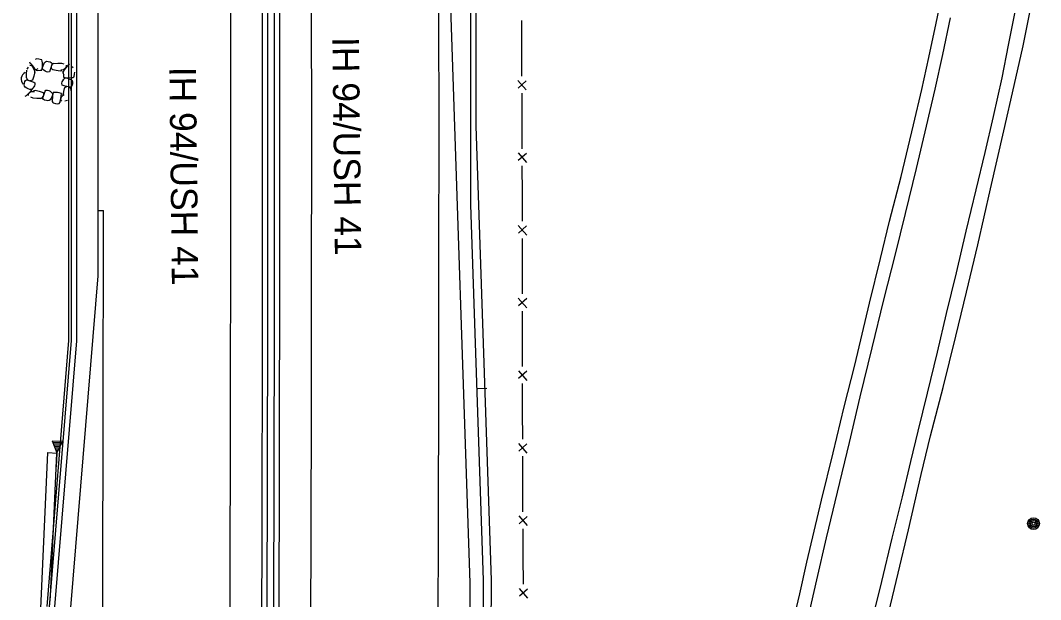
# Model space of a CAD drawing. Extents: x 588843 to 2552415, y 180129 to 269402.
# Drawn here: x 593926.7 to 594311.3, y 187872.4 to 188090.9 of the extents above; entities that cross this region are included whole.
import ezdxf

# ---------------------------------------------------------------- set-up
doc = ezdxf.new("R2010")
doc.units = 0
for name, color, linetype in [('Default', 7, 'Continuous'), ('E_DRN', 7, 'Continuous'), ('E_DRN_RipRap', 7, 'Continuous'), ('E_FEN_P', 7, 'Continuous'), ('E_MISCPROP', 7, 'Continuous'), ('E_RDWY', 7, 'Continuous'), ('E_RDWY_Gravel', 7, 'Continuous'), ('E_RDWY_Text', 7, 'Continuous'), ('P_BMGRD', 7, 'Continuous'), ('P_RDWY_BarrierConc', 7, 'Continuous'), ('P_RDWY_C_and_G', 7, 'Continuous'), ('P_RDWY_C_and_GBack', 7, 'Continuous'), ('P_RDWY_C_and_GFace', 7, 'Continuous'), ('P_RDWY_PavtEdge', 7, 'Continuous'), ('P_RDWY_ShldAgg', 7, 'Continuous'), ('P_RDWY_ShldPaved', 7, 'Continuous')]:
    doc.layers.add(name, color=color, linetype=linetype)

# ---------------------------------------------------------------- blocks, each defined once
blk = doc.blocks.new('POLE')
at = {"layer": 'Default'}
for radius in [4.46, 3.35, 2.23, 1.12]:
    blk.add_circle((0, 0), radius, dxfattribs=at)
blk = doc.blocks.new('CULV2')
at = {"layer": 'E_DRN'}
blk.add_arc((19.7, 14.8), 24.6, 216.8699, 323.1301, dxfattribs=at)

msp = doc.modelspace()

# ---------------------------------------------------------------- linework, layer by layer
at = {"layer": 'E_DRN_RipRap'}
for p, q in [((593932.94, 188076.36), (593932.27, 188076.17)), ((593933.7, 188076.29), (593932.94, 188076.36)), ((593934.63, 188076.07), (593933.7, 188076.29)), ((593934.75, 188075.98), (593934.63, 188076.07)), ((593934.96, 188075.55), (593934.75, 188075.98)), ((593928.97, 188070.74), (593929.1, 188072.07)), ((593929.22, 188072.49), (593929.75, 188073.3)), ((593930.19, 188075.3), (593930.34, 188074.69)), ((593930.28, 188073.98), (593930.89, 188073.91)), ((593930.34, 188074.69), (593930.61, 188074.44)), ((593930.61, 188074.44), (593931.27, 188073.7)), ((593930.89, 188073.91), (593931.45, 188073.25)), ((593931.27, 188073.7), (593931.86, 188072.92)), ((593931.45, 188073.25), (593931.69, 188072.61)), ((593931.63, 188072.74), (593932.02, 188071.85)), ((593931.86, 188072.92), (593932.57, 188072.29)), ((593932.57, 188072.29), (593933.38, 188072.77)), ((593932.59, 188072.1), (593933.13, 188071.99)), ((593933.13, 188071.99), (593934.11, 188072.09)), ((593934.11, 188072.09), (593934.77, 188072.12)), ((593934.77, 188072.12), (593935.03, 188073.37)), ((593934.97, 188074.92), (593934.96, 188075.55)), ((593935, 188074.05), (593934.97, 188074.92)), ((593935.03, 188073.37), (593935, 188074.05)), ((593935.02, 188073.16), (593935.22, 188073.8)), ((593935.09, 188072.6), (593935.02, 188073.16)), ((593935.21, 188072.46), (593935.09, 188072.6)), ((593935.53, 188072.13), (593935.21, 188072.46)), ((593935.22, 188073.8), (593935.49, 188074.39)), ((593935.49, 188074.39), (593935.79, 188075.02)), ((593936.03, 188071.76), (593935.53, 188072.13)), ((593935.79, 188075.02), (593936.1, 188075.27)), ((593936.1, 188075.27), (593936.6, 188075.45)), ((593936.6, 188075.45), (593937.15, 188075.38)), ((593937.15, 188075.38), (593937.88, 188075.23)), ((593938.11, 188072.65), (593937.82, 188071.85)), ((593937.88, 188075.23), (593938.33, 188074.97)), ((593938.52, 188074.2), (593938.11, 188072.65)), ((593938.46, 188073.96), (593938.25, 188073.21)), ((593938.59, 188072.43), (593938.25, 188073.21)), ((593938.33, 188074.97), (593938.53, 188074.7)), ((593938.85, 188074.44), (593938.46, 188073.96)), ((593938.53, 188074.7), (593938.52, 188074.2)), ((593938.97, 188072.28), (593938.59, 188072.43)), ((593939.36, 188074.69), (593938.85, 188074.44)), ((593940.13, 188071.99), (593938.97, 188072.28)), ((593939.36, 188074.69), (593940.84, 188074.81)), ((593941.69, 188071.74), (593940.13, 188071.99)), ((593940.84, 188074.81), (593942.17, 188074.75)), ((593942.9, 188072.3), (593941.94, 188072.17)), ((593942.17, 188074.75), (593943.1, 188074.46)), ((593943.24, 188072.2), (593942.77, 188071.38)), ((593943.47, 188072.67), (593942.9, 188072.3)), ((593943.87, 188072.94), (593943.24, 188072.2)), ((593944, 188073.35), (593943.47, 188072.67)), ((593944.46, 188073.74), (593943.87, 188072.94)), ((593943.95, 188073.96), (593944, 188073.35)), ((593944.65, 188074.06), (593944.46, 188073.74)), ((593945.22, 188074.33), (593944.65, 188074.06)), ((593946.55, 188073), (593946.01, 188073.44)), ((593928.38, 188067.8), (593928.67, 188068.24)), ((593928.67, 188068.24), (593928.95, 188068.42)), ((593928.95, 188068.42), (593929.45, 188068.39)), ((593929, 188069.26), (593928.97, 188070.74)), ((593929, 188069.26), (593929.23, 188068.73)), ((593929.23, 188068.73), (593929.68, 188068.31)), ((593929.45, 188068.39), (593930.98, 188067.89)), ((593929.68, 188068.31), (593930.42, 188068.07)), ((593931.22, 188068.37), (593930.42, 188068.07)), ((593931.39, 188068.74), (593931.22, 188068.37)), ((593931.74, 188069.88), (593931.39, 188068.74)), ((593932.08, 188071.43), (593931.74, 188069.88)), ((593932.02, 188071.85), (593932, 188071.23)), ((593936.51, 188071.52), (593936.03, 188071.76)), ((593936.98, 188071.38), (593936.51, 188071.52)), ((593937.66, 188071.49), (593936.98, 188071.38)), ((593937.82, 188071.85), (593937.66, 188071.49)), ((593942.3, 188071.88), (593941.69, 188071.74)), ((593942.45, 188067.66), (593942.67, 188068.15)), ((593942.56, 188071.76), (593942.85, 188070.87)), ((593942.67, 188068.15), (593943.03, 188068.66)), ((593942.82, 188071.05), (593942.95, 188070.07)), ((593942.85, 188070.87), (593943.07, 188070.36)), ((593942.95, 188070.07), (593943, 188069.42)), ((593943, 188069.42), (593944.25, 188069.19)), ((593943.03, 188068.66), (593943.36, 188068.99)), ((593943.36, 188068.99), (593943.49, 188069.11)), ((593943.49, 188069.11), (593944.05, 188069.2)), ((593944.05, 188069.2), (593944.69, 188069.02)), ((593944.25, 188069.19), (593944.94, 188069.25)), ((593944.69, 188069.02), (593945.29, 188068.76)), ((593944.94, 188069.25), (593945.8, 188069.3)), ((593945.29, 188068.76), (593945.93, 188068.48)), ((593945.8, 188069.3), (593946.43, 188069.33)), ((593945.93, 188068.48), (593946.18, 188068.18)), ((593946.18, 188068.18), (593946.38, 188067.68)), ((593946.43, 188069.33), (593946.86, 188069.55)), ((593946.86, 188069.55), (593946.94, 188069.68)), ((593946.94, 188069.68), (593947.13, 188070.61)), ((593947.13, 188070.61), (593947.18, 188071.37)), ((593928.1, 188066.54), (593928.19, 188067.09)), ((593928.25, 188066.03), (593928.1, 188066.54)), ((593928.19, 188067.09), (593928.38, 188067.8)), ((593928.48, 188065.71), (593928.25, 188066.03)), ((593929.1, 188065.37), (593928.48, 188065.71)), ((593929.67, 188065.07), (593929.1, 188065.37)), ((593930.3, 188064.84), (593929.67, 188065.07)), ((593930.86, 188064.88), (593930.3, 188064.84)), ((593930.67, 188064.2), (593931.24, 188064.95)), ((593931, 188064.99), (593930.86, 188064.88)), ((593930.98, 188067.89), (593931.76, 188067.56)), ((593931.36, 188065.29), (593931, 188064.99)), ((593931.76, 188065.77), (593931.36, 188065.29)), ((593931.6, 188064.44), (593932.22, 188064.54)), ((593931.76, 188067.56), (593932.11, 188067.39)), ((593932.02, 188066.24), (593931.76, 188065.77)), ((593932.18, 188066.7), (593932.02, 188066.24)), ((593932.11, 188067.39), (593932.18, 188066.7)), ((593932.22, 188064.54), (593933.76, 188064.19)), ((593936.08, 188064.18), (593936.25, 188064.53)), ((593936.25, 188064.53), (593936.95, 188064.6)), ((593936.95, 188064.6), (593937.4, 188064.43)), ((593937.4, 188064.43), (593937.87, 188064.17)), ((593942.33, 188067.19), (593942.45, 188067.66)), ((593942.46, 188066.5), (593942.33, 188067.19)), ((593942.82, 188066.36), (593942.46, 188066.5)), ((593943.63, 188066.1), (593942.82, 188066.36)), ((593943.03, 188064.05), (593943.28, 188065.22)), ((593943.28, 188065.22), (593943.43, 188065.6)), ((593943.43, 188065.6), (593944.2, 188065.97)), ((593945.19, 188065.73), (593943.63, 188066.1)), ((593944.95, 188065.79), (593944.2, 188065.97)), ((593945.43, 188065.41), (593944.95, 188065.79)), ((593945.68, 188065.74), (593945.19, 188065.73)), ((593945.71, 188064.9), (593945.43, 188065.41)), ((593945.95, 188065.94), (593945.68, 188065.74)), ((593945.71, 188064.9), (593945.87, 188063.43)), ((593946.2, 188066.4), (593945.95, 188065.94)), ((593946.33, 188067.13), (593946.2, 188066.4)), ((593946.38, 188067.68), (593946.33, 188067.13)), ((593928.44, 188062.33), (593929.04, 188062.53)), ((593929.04, 188062.53), (593929.27, 188062.83)), ((593929.27, 188062.83), (593929.95, 188063.55)), ((593929.74, 188062.54), (593929.76, 188063.15)), ((593929.76, 188063.15), (593930.38, 188063.76)), ((593929.95, 188063.55), (593930.67, 188064.2)), ((593930.38, 188063.76), (593931, 188064.05)), ((593931.55, 188061.57), (593930.64, 188061.92)), ((593931, 188064.05), (593931.96, 188064.06)), ((593932.87, 188061.42), (593931.55, 188061.57)), ((593934.35, 188061.45), (593932.87, 188061.42)), ((593933.76, 188064.19), (593934.9, 188063.83)), ((593934.35, 188061.45), (593934.88, 188061.67)), ((593934.88, 188061.67), (593935.31, 188062.12)), ((593934.9, 188063.83), (593935.27, 188063.65)), ((593935.19, 188061.39), (593935.23, 188061.89)), ((593935.37, 188061.11), (593935.19, 188061.39)), ((593935.23, 188061.89), (593935.74, 188063.41)), ((593935.27, 188063.65), (593935.56, 188062.85)), ((593935.31, 188062.12), (593935.56, 188062.85)), ((593935.8, 188060.81), (593935.37, 188061.11)), ((593935.74, 188063.41), (593936.08, 188064.18)), ((593936.52, 188060.62), (593935.8, 188060.81)), ((593937.06, 188060.52), (593936.52, 188060.62)), ((593937.58, 188060.67), (593937.06, 188060.52)), ((593937.9, 188060.89), (593937.58, 188060.67)), ((593937.87, 188064.17), (593938.34, 188063.76)), ((593938.24, 188061.5), (593937.9, 188060.89)), ((593938.55, 188062.07), (593938.24, 188061.5)), ((593938.34, 188063.76), (593938.64, 188063.41)), ((593938.79, 188062.7), (593938.55, 188062.07)), ((593938.64, 188063.41), (593938.75, 188063.26)), ((593938.72, 188060.94), (593938.69, 188060.31)), ((593938.75, 188061.81), (593938.72, 188060.94)), ((593938.75, 188063.26), (593938.79, 188062.7)), ((593938.76, 188062.5), (593938.75, 188061.81)), ((593939.1, 188063.72), (593938.76, 188062.5)), ((593939.76, 188063.71), (593939.1, 188063.72)), ((593940.74, 188063.75), (593939.76, 188063.71)), ((593941.27, 188063.6), (593940.74, 188063.75)), ((593942.16, 188063.28), (593941.27, 188063.6)), ((593941.72, 188060.03), (593941.74, 188060.4)), ((593941.74, 188060.4), (593941.89, 188061.38)), ((593941.89, 188061.38), (593942.11, 188062.33)), ((593941.96, 188060.95), (593942.13, 188061.8)), ((593942.3, 188060.43), (593941.96, 188060.95)), ((593942.11, 188062.33), (593942.16, 188063.28)), ((593942.13, 188061.8), (593942.47, 188062.39)), ((593942.47, 188062.39), (593943.25, 188062.95)), ((593942.71, 188062.95), (593943.13, 188063.41)), ((593942.82, 188062.48), (593943.03, 188064.05)), ((593944.44, 188060.65), (593943.51, 188060.38)), ((593945.87, 188063.43), (593945.85, 188062.09)), ((593938.69, 188060.31), (593938.87, 188059.87)), ((593938.87, 188059.87), (593938.99, 188059.77)), ((593938.99, 188059.77), (593939.91, 188059.5)), ((593939.91, 188059.5), (593940.66, 188059.37)), ((593940.66, 188059.37), (593941.34, 188059.52)), ((593941.34, 188059.52), (593941.72, 188060.03))]:
    msp.add_line(p, q, dxfattribs=at)
at = {"layer": 'E_FEN_P'}
for p, q in [((594114.21, 188068.27), (594117.39, 188064.64)), ((594117.38, 188068.11), (594114.29, 188065.37)), ((594114.29, 188040.89), (594117.47, 188037.25)), ((594117.46, 188040.73), (594114.37, 188037.98)), ((594114.37, 188013.5), (594117.56, 188009.87)), ((594117.55, 188013.34), (594114.45, 188010.59)), ((594114.41, 187986.12), (594117.59, 187982.48)), ((594117.58, 187985.96), (594114.48, 187983.21)), ((594114.44, 187958.73), (594117.61, 187955.09)), ((594117.61, 187958.57), (594114.51, 187955.83)), ((594114.47, 187931.35), (594117.64, 187927.71)), ((594117.64, 187931.18), (594114.54, 187928.44)), ((594114.59, 187903.96), (594117.78, 187900.33)), ((594117.76, 187903.81), (594114.67, 187901.05)), ((594114.72, 187876.57), (594117.92, 187872.95)), ((594117.9, 187876.42), (594114.81, 187873.67))]:
    msp.add_line(p, q, dxfattribs=at)
for points in [[(594115.61, 188090.8), (594115.64, 188080.34)], [(594115.64, 188080.34), (594115.67, 188069.89)], [(594115.69, 188063.41), (594115.72, 188053.7), (594115.72, 188052.96)], [(594115.72, 188052.96), (594115.75, 188042.5)], [(594115.77, 188036.03), (594115.8, 188025.57)], [(594115.8, 188025.57), (594115.83, 188015.11)], [(594115.85, 188008.64), (594115.85, 188008.61), (594115.86, 187998.19)], [(594115.86, 187998.19), (594115.87, 187987.73)], [(594115.88, 187981.26), (594115.89, 187970.8)], [(594115.89, 187970.8), (594115.9, 187960.34)], [(594115.91, 187953.87), (594115.92, 187943.41)], [(594115.92, 187943.41), (594115.93, 187932.96)], [(594115.94, 187926.49), (594115.99, 187916.03)], [(594115.99, 187916.03), (594116.04, 187905.57)], [(594116.08, 187899.1), (594116.13, 187888.64)], [(594116.13, 187888.64), (594116.18, 187878.19)]]:
    msp.add_lwpolyline(points, dxfattribs=at)
at = {"layer": 'E_RDWY'}
for points in [[(594228.57, 187780.63), (594232.33, 187798.24), (594235.82, 187813.68), (594239.52, 187829.79), (594243.61, 187847.13), (594247.57, 187863.55), (594251.39, 187879.2), (594255.33, 187895.54), (594259.23, 187911.13), (594262.33, 187924.57), (594265.09, 187935.9), (594268.62, 187950.26), (594272.41, 187965.71), (594275.87, 187980.35), (594279.56, 187995.66), (594283.28, 188011.39), (594287.05, 188026.98), (594290.42, 188041.06), (594293.56, 188054.66), (594296.78, 188069.2), (594299.2, 188081.49), (594302.12, 188095.96)], [(594204.12, 187779.52), (594208.85, 187801.44), (594212.44, 187817.45), (594216.12, 187833.75), (594219.89, 187849.7), (594223.26, 187863.88), (594226.91, 187879.94), (594230.58, 187895.72), (594234.73, 187912.94), (594239.27, 187931.72), (594243.32, 187948.86), (594247.83, 187967.41), (594252.22, 187985.44), (594256.55, 188002.76), (594260.32, 188018.1), (594264.49, 188035.08), (594268.29, 188050.96), (594271.53, 188064.91), (594274.5, 188078.06), (594277.28, 188091.89)]]:
    msp.add_lwpolyline(points, dxfattribs=at)
at = {"layer": 'E_RDWY_Gravel'}
for points in [[(594198.98, 187780.6), (594201.99, 187794.32), (594206.34, 187814.37), (594209.66, 187828.73), (594213.65, 187845.12), (594217.26, 187860.85), (594220.48, 187874.65), (594223.16, 187886.54), (594228.75, 187909.95), (594233.11, 187927.78), (594237.26, 187945.12), (594241.24, 187960.82), (594246.83, 187984.18), (594250.95, 188001.08), (594254.37, 188015.14), (594258.72, 188032.07), (594263.37, 188051.46), (594266.51, 188064.82), (594269.19, 188076.95), (594271.88, 188089.88), (594274.28, 188101.34)], [(594233.94, 187780.16), (594237.95, 187799.28), (594241.84, 187816.34), (594245.91, 187834.4), (594249.71, 187849.82), (594253.29, 187864.57), (594257.55, 187882.4), (594261.56, 187898.79), (594266.33, 187919.58), (594269.83, 187934.17), (594274.56, 187952.44), (594279.37, 187971.78), (594283.38, 187988.43), (594287.61, 188006.29), (594292.43, 188027.41), (594297.44, 188049.17), (594301.38, 188066.31), (594304.71, 188081.27), (594307.22, 188093.84)]]:
    msp.add_lwpolyline(points, dxfattribs=at)
at = {"layer": 'P_BMGRD'}
for p, q in [((593938.69, 187932.3), (593940.47, 187927.72)), ((593938.69, 187932.3), (593942.64, 187932.13)), ((593938.89, 187931.79), (593942.4, 187931.64)), ((593939.09, 187931.28), (593942.16, 187931.14)), ((593939.29, 187930.77), (593941.91, 187930.65)), ((593939.48, 187930.26), (593941.68, 187930.16)), ((593939.68, 187929.76), (593941.43, 187929.68)), ((593940.47, 187927.72), (593942.64, 187932.13)), ((593938.06, 187873.74), (593940.47, 187927.71)), ((593939.88, 187929.25), (593941.19, 187929.19)), ((593940.08, 187928.73), (593940.95, 187928.7)), ((593940.47, 187927.71), (593940.24, 187922.45)), ((593940.27, 187928.23), (593940.71, 187928.21)), ((593937.73, 187869.73), (593938.05, 187873.72))]:
    msp.add_line(p, q, dxfattribs=at)
msp.add_arc((593937.06, 187873.8), 1, 355.3153, 356.6194, dxfattribs=at)
at = {"layer": 'P_RDWY_BarrierConc'}
for radius in [57298.53, 57300.53, 57303.03, 57305.03]:
    msp.add_arc((536719.48, 188049.55), radius, 359.769059, 0.6479963, dxfattribs=at)
at = {"layer": 'P_RDWY_C_and_G'}
msp.add_line((593939.73, 187869.64), (593947.95, 187970.05), dxfattribs=at)
msp.add_arc((536719.48, 188049.55), 57228.53, 359.920406, 0.647996, dxfattribs=at)
at = {"layer": 'P_RDWY_C_and_GBack'}
msp.add_line((593936.73, 187869.81), (593944.96, 187970.21), dxfattribs=at)
msp.add_arc((536719.48, 188049.55), 57225.53, 359.920487, 0.647996, dxfattribs=at)
at = {"layer": 'P_RDWY_C_and_GFace'}
msp.add_line((593937.73, 187869.73), (593945.95, 187970.13), dxfattribs=at)
msp.add_arc((536719.48, 188049.55), 57226.53, 359.920487, 0.647996, dxfattribs=at)
at = {"layer": 'P_RDWY_PavtEdge'}
for p, q in [((594096.29, 187878.74), (594086.37, 188174.07)), ((593956, 188019.19), (593958, 188019.19)), ((593945.73, 187869.39), (593955.98, 187994.56)), ((594099.09, 187952.01), (594102.58, 187952.14)), ((593936.98, 187927.92), (593940.47, 187927.71)), ((594095.08, 187578.66), (594096.29, 187878.74))]:
    msp.add_line(p, q, dxfattribs=at)
msp.add_lwpolyline([(593934.22, 187866.24), (593936.98, 187927.92)], dxfattribs=at)
for radius, start, end in [(57236.53, 359.944955, 0.647996), (57286.53, 359.769059, 0.647996), (57317.03, 359.769059, 0.6479963), (57365.03, 359.769059, 0.1893986), (57238.53, 359.769059, 359.969612)]:
    msp.add_arc((536719.48, 188049.55), radius, start, end, dxfattribs=at)
at = {"layer": 'P_RDWY_ShldAgg'}
msp.add_line((594104.26, 187879.74), (594098.51, 188051.01), dxfattribs=at)
for radius, start, end in [(57379.03, 0.0014575, 0.2693238), (57385.03, 359.769059, 359.8304528)]:
    msp.add_arc((536719.48, 188049.55), radius, start, end, dxfattribs=at)
at = {"layer": 'P_RDWY_ShldPaved'}
msp.add_line((594101.26, 187879.69), (594096.5, 188021.37), dxfattribs=at)
for radius, start, end in [(57377.03, 359.9718622, 0.2693246), (57382.03, 359.769059, 359.8303981)]:
    msp.add_arc((536719.48, 188049.55), radius, start, end, dxfattribs=at)

# ---------------------------------------------------------------- block references
at = {"layer": 'E_DRN', "xscale": 0.11167174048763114, "yscale": 0.11167174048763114, "rotation": -99.08560916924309}
msp.add_blockref('CULV2', (593928.48, 188071.23), dxfattribs=at)
at = {"layer": 'E_MISCPROP', "xscale": 0.5000000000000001, "yscale": 0.5, "rotation": -102.57777672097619}
msp.add_blockref('POLE', (594308.63, 187901.08), dxfattribs=at)

# ---------------------------------------------------------------- texts
at = {"layer": 'E_RDWY_Text'}
for p in [(594044.3, 188084.56), (593982.85, 188073.33)]:
    msp.add_text('IH 94/USH 41', height=10, rotation=270.6765, dxfattribs=at).set_placement(p)

doc.saveas('drawing.dxf')
